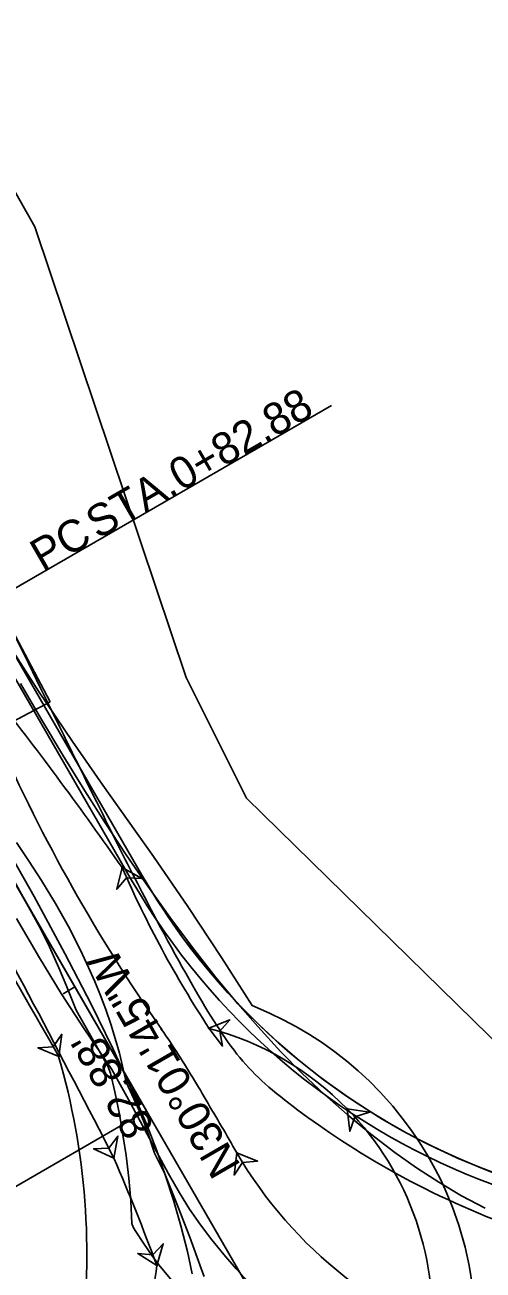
# Model space of a CAD drawing. Extents: x 208278 to 2196496, y 417130 to 637870.
# Drawn here: x 209173.8 to 209214, y 417343.4 to 417452.6 of the extents above; entities that cross this region are included whole.
import ezdxf

# ---------------------------------------------------------------- set-up
doc = ezdxf.new("R2010")
doc.units = 0
for name, color, linetype in [('BR_P_Beam', 7, 'Continuous'), ('DR_P_Ditch', 7, 'Continuous'), ('DR_P_Filter_Fabric_Fence', 7, 'Continuous'), ('DR_P_Trench_Drain', 7, 'Continuous'), ('LT_P_Conduit', 7, 'Continuous'), ('PM_P_Edge_Line', 7, 'Continuous'), ('PV_P_Saw_Cut_Line', 7, 'Continuous'), ('PV_P_Walk', 7, 'Continuous'), ('RD_P_Concrete_Barrier', 7, 'Continuous'), ('RD_P_Fence', 7, 'Continuous'), ('RD_P_Gate', 7, 'Continuous'), ('UT_P_Gas', 7, 'Continuous'), ('UT_P_Pressure Pipes', 7, 'Continuous'), ('UT_P_Sanitary', 7, 'Continuous'), ('UT_P_Water', 7, 'Continuous'), ('XS_P_Section', 7, 'Continuous')]:
    doc.layers.add(name, color=color, linetype=linetype)

msp = doc.modelspace()

# ---------------------------------------------------------------- linework, layer by layer
at = {"layer": 'BR_P_Beam'}
msp.add_line((209183.19, 417377.59), (209169.55, 417401.19), dxfattribs=at)
msp.add_line((209183.19, 417377.59), (209169.55, 417401.19), dxfattribs=at)
msp.add_arc((209236, 417408.12), 61, 210.029, 287.1031, dxfattribs=at)
at = {"layer": 'DR_P_Ditch'}
msp.add_line((209203.23, 417324.93), (209161.75, 417396.69), dxfattribs=at)
at = {"layer": 'DR_P_Filter_Fabric_Fence'}
for points in [[(209173.1, 417380.88), (209174.21, 417379.22), (209175.29, 417377.54), (209176.5, 417375.54), (209177.64, 417373.51), (209178.71, 417371.44), (209179.42, 417369.93), (209179.96, 417368.71), (209180.46, 417367.47), (209180.93, 417366.23), (209181.37, 417364.97), (209181.76, 417363.69), (209182.12, 417362.41), (209182.65, 417360.13), (209182.75, 417359.82), (209183.85, 417357.39), (209184.24, 417356.47), (209184.59, 417355.53), (209185.2, 417353.64), (209186.09, 417351.85), (209187.22, 417349.07), (209188.3, 417346.27), (209189.33, 417343.46), (209189.56, 417342.83)], [(209181.64, 417353.2), (209181.99, 417355.14), (209181.19, 417354.08), (209179.85, 417354.04), (209181.64, 417353.2)], [(209185.39, 417343.81), (209185.97, 417345.7), (209185.05, 417344.74), (209183.72, 417344.86), (209185.39, 417343.81)]]:
    msp.add_lwpolyline(points, dxfattribs=at)
for points in [[(209181.64, 417353.2), (209181.99, 417355.14), (209181.19, 417354.08), (209179.85, 417354.04)], [(209185.39, 417343.81), (209185.97, 417345.7), (209185.05, 417344.74), (209183.72, 417344.86)]]:
    msp.add_lwpolyline(points, close=True, dxfattribs=at)
for centre in [(209181.64, 417353.2), (209181.64, 417353.2), (209185.39, 417343.81), (209185.39, 417343.81)]:
    msp.add_circle(centre, 0.0417, dxfattribs=at)
for centre, radius, start, end in [((208051.5, 416772.87), 1270.43, 27.18053, 28.55626), ((209012.62, 417280.2), 184.11, 20.2135, 23.3596), ((209157.52, 417346.8), 28.03, 318.8875, 353.8854)]:
    msp.add_arc(centre, radius, start, end, dxfattribs=at)
at = {"layer": 'DR_P_Trench_Drain'}
for points in [[(209173.44, 417394.84), (209175.28, 417391.67), (209177.16, 417388.53), (209179.09, 417385.41), (209180.88, 417382.6), (209182.72, 417379.81), (209184.6, 417377.06), (209186.53, 417374.35), (209188.53, 417371.68), (209190.58, 417369.06), (209192.5, 417366.75), (209194.25, 417364.74), (209196.29, 417362.54), (209198.16, 417360.64), (209200.1, 417358.8), (209202.09, 417357.03), (209204.15, 417355.33), (209206.27, 417353.72), (209208.18, 417352.37), (209210.13, 417351.1), (209212.14, 417349.92), (209214.2, 417348.82)], [(209193.51, 417342.29), (209192.37, 417343.5), (209191.27, 417344.75), (209190.22, 417346.05), (209189.22, 417347.38), (209188.27, 417348.75), (209187.38, 417350.16), (209186.38, 417351.89), (209182.92, 417358.36), (209181.44, 417360.97), (209179.02, 417364.56), (209177.02, 417367.64), (209175.11, 417370.76), (209173.1, 417374.22)], [(209192.41, 417353.69), (209192.24, 417353.98), (209192.07, 417354.26), (209191.91, 417354.55), (209191.74, 417354.84), (209191.57, 417355.13), (209191.41, 417355.42), (209191.24, 417355.71), (209191.07, 417355.99), (209190.9, 417356.28), (209190.74, 417356.57), (209190.57, 417356.86), (209190.4, 417357.15), (209190.23, 417357.43), (209190.06, 417357.72), (209189.9, 417358.01), (209189.73, 417358.3), (209189.56, 417358.58), (209189.39, 417358.87), (209189.22, 417359.16), (209189.05, 417359.44), (209188.88, 417359.73), (209188.7, 417360.02), (209188.53, 417360.3), (209188.36, 417360.58), (209188.18, 417360.87), (209188.01, 417361.15), (209187.83, 417361.44), (209187.65, 417361.72), (209187.48, 417362), (209187.3, 417362.28), (209187.12, 417362.56), (209186.93, 417362.84), (209186.75, 417363.12), (209186.57, 417363.4), (209186.38, 417363.67), (209186.2, 417363.95), (209186.01, 417364.23), (209185.82, 417364.5)], [(209192.41, 417353.69), (209192.17, 417351.73), (209192.91, 417352.84), (209194.24, 417352.95), (209192.41, 417353.69)]]:
    msp.add_lwpolyline(points, dxfattribs=at)
msp.add_lwpolyline([(209192.41, 417353.69), (209192.17, 417351.73), (209192.91, 417352.84), (209194.24, 417352.95)], close=True, dxfattribs=at)
for centre in [(209185.82, 417364.5), (209185.82, 417364.5), (209192.41, 417353.69), (209192.41, 417353.69)]:
    msp.add_circle(centre, 0.0417, dxfattribs=at)
for centre, radius, start, end in [((209310.51, 417451.56), 152.07, 203.8397, 214.9244), ((209225.78, 417373.22), 38.67, 210.338, 253.3438)]:
    msp.add_arc(centre, radius, start, end, dxfattribs=at)
at = {"layer": 'LT_P_Conduit'}
for points in [[(209171.05, 417380.81), (209174.3, 417374.99), (209175.25, 417373.22), (209175.98, 417371.73), (209176.81, 417369.91), (209177.46, 417368.37), (209178.31, 417366.2), (209181.1, 417361.27), (209181.33, 417360.65), (209181.72, 417359.02), (209182.12, 417357.07), (209182.46, 417355.09), (209182.7, 417353.45), (209182.93, 417351.46), (209183.11, 417349.47), (209183.22, 417347.47), (209183.33, 417347.16), (209183.49, 417346.87), (209184.22, 417345.75), (209184.98, 417344.66), (209185.58, 417343.86), (209186.87, 417342.32)], [(209176.79, 417362.13), (209177.06, 417364.08), (209176.3, 417362.98), (209174.97, 417362.89), (209176.79, 417362.13)]]:
    msp.add_lwpolyline(points, dxfattribs=at)
msp.add_lwpolyline([(209176.79, 417362.13), (209177.06, 417364.08), (209176.3, 417362.98), (209174.97, 417362.89)], close=True, dxfattribs=at)
msp.add_circle((209176.79, 417362.13), 0.0417, dxfattribs=at)
msp.add_circle((209176.79, 417362.13), 0.0417, dxfattribs=at)
for centre, radius, start, end in [((212853.66, 419471.37), 4238.89, 209.40902, 209.84083), ((209117.29, 417344.79), 61.97, 352.412, 16.2407)]:
    msp.add_arc(centre, radius, start, end, dxfattribs=at)
at = {"layer": 'PM_P_Edge_Line'}
msp.add_lwpolyline([(209093.86, 417513.4), (209102.11, 417463.85), (209121.09, 417416.38), (209142.14, 417379.63), (209146.67, 417363.53), (209141.31, 417347.02), (209130.17, 417339.58), (209102, 417333.59), (209104.94, 417313.99), (209118.52, 417316.8), (209124.41, 417286.75), (209135.92, 417289.64), (209129.73, 417318.94), (209154.07, 417324.14), (209248.91, 417348.5), (209255.78, 417350.71), (209251.98, 417364.94), (209222.73, 417364.32), (209215.99, 417362.52), (209193.28, 417384.78), (209187.97, 417395.34), (209174.69, 417434.86), (209154.88, 417469.95), (209142.09, 417520.32)], dxfattribs=at)
at = {"layer": 'PV_P_Saw_Cut_Line'}
msp.add_line((209184.49, 417357.36), (209163.6, 417345.28), dxfattribs=at)
at = {"layer": 'PV_P_Walk'}
msp.add_line((209184.49, 417357.36), (209161.75, 417396.69), dxfattribs=at)
at = {"layer": 'RD_P_Concrete_Barrier'}
msp.add_open_spline([(209234.88, 417345.39), (209234.01, 417345.19), (209227.34, 417343.94), (209217.17, 417346.68), (209205.96, 417351.72), (209197.03, 417357.79), (209192.58, 417361.64), (209188.78, 417367.79), (209183.44, 417377.55), (209174.42, 417396.1), (209159.19, 417426.85), (209153.46, 417438.94), (209149.59, 417448.54), (209146.25, 417457.61), (209143.4, 417465.3), (209141.32, 417472.35), (209137.69, 417485.14), (209134.73, 417496.5), (209133.52, 417504.6), (209132.25, 417511.59), (209129.53, 417525.99), (209128.93, 417536.89), (209127.97, 417550.14), (209127.15, 417563.74), (209126.69, 417575.36), (209126.58, 417587.85), (209125.68, 417599.13), (209125.46, 417606.14), (209126.12, 417618.12), (209127.26, 417625.09), (209128.61, 417631.46), (209130.06, 417637.26), (209131.51, 417643.04), (209133.54, 417649.69), (209135.69, 417657.63), (209138.67, 417666.68), (209142.04, 417677.38), (209145.58, 417687.23), (209148, 417696), (209151.39, 417705.34), (209154.03, 417715.46), (209155.6, 417721.82), (209158.19, 417730.91), (209160.32, 417739.83), (209162.59, 417753.27), (209164.57, 417764.31), (209166.03, 417774.02), (209167.62, 417787.04), (209168.73, 417803.91), (209168.81, 417820.87), (209168.35, 417842.99), (209166.81, 417866.5), (209166.19, 417876.32), (209164.07, 417889.49), (209156.1, 417937.11), (209150.23, 417975.1), (209147.45, 417990.32), (209143.97, 418013.05), (209132.35, 418066.18), (209123, 418098.65), (209115.49, 418122.03), (209106.32, 418147.11), (209093.3, 418176.42), (209084.02, 418193.49), (209069.15, 418219.75), (209053.74, 418246), (209037.24, 418270.97), (209030.06, 418281.45), (209013.83, 418304.34), (208994.17, 418331.42), (208973.78, 418359.3), (208954.58, 418382.21), (208943.5, 418397.76), (208928.18, 418416.86), (208906.93, 418443.65), (208892.96, 418463.4), (208879.19, 418481.37), (208868.85, 418494.84), (208848.86, 418520.14), (208832.28, 418541.08), (208811.75, 418565.55), (208795.09, 418586.36), (208786.41, 418596.81), (208787.6, 418606.91), (208789.23, 418611.23), (208813.36, 418644.77)], degree=3, dxfattribs=at)
at = {"layer": 'RD_P_Fence'}
for p, q in [((209176.03, 417393.21), (209157.46, 417428.17)), ((209168.6, 417389.26), (209176.03, 417393.21))]:
    msp.add_line(p, q, dxfattribs=at)
for points in [[(209172.33, 417398.37), (209175.03, 417394.16), (209177.99, 417389.73), (209180.65, 417385.9), (209185.1, 417379.65), (209188.12, 417375.26), (209191.06, 417370.81), (209193.75, 417366.59), (209195.27, 417365.92), (209196.48, 417365.35), (209197.65, 417364.72), (209198.8, 417364.05), (209199.92, 417363.32), (209201, 417362.54), (209202.06, 417361.72), (209203.07, 417360.86), (209204.05, 417359.95), (209204.98, 417359), (209206.09, 417357.76), (209206.93, 417356.72), (209207.73, 417355.65), (209208.47, 417354.55), (209209.17, 417353.41), (209209.82, 417352.25), (209210.27, 417351.36), (209210.7, 417350.45), (209211.34, 417348.91), (209211.89, 417347.34), (209212.44, 417345.42), (209212.81, 417343.79), (209213.13, 417341.82)], [(209188.51, 417343.07), (209188.09, 417345.03), (209187.51, 417347.29), (209186.86, 417349.53), (209186.14, 417351.75), (209185.36, 417353.94), (209184.51, 417356.12), (209183.22, 417359.19), (209181.55, 417362.83), (209179.64, 417366.72), (209177.33, 417371.15), (209174.64, 417376.14), (209167.88, 417388.01)], [(209182.35, 417378.69), (209181.88, 417376.78), (209182.75, 417377.79), (209184.08, 417377.74), (209182.35, 417378.69)], [(209189.97, 417364.6), (209191.17, 417363.03), (209190.93, 417364.34), (209191.8, 417365.35), (209189.97, 417364.6)], [(209202.1, 417357.53), (209202.32, 417355.57), (209202.78, 417356.82), (209204.05, 417357.24), (209202.1, 417357.53)]]:
    msp.add_lwpolyline(points, dxfattribs=at)
for points in [[(209182.35, 417378.69), (209181.88, 417376.78), (209182.75, 417377.79), (209184.08, 417377.74)], [(209189.97, 417364.6), (209191.17, 417363.03), (209190.93, 417364.34), (209191.8, 417365.35)], [(209202.1, 417357.53), (209202.32, 417355.57), (209202.78, 417356.82), (209204.05, 417357.24)]]:
    msp.add_lwpolyline(points, close=True, dxfattribs=at)
for centre in [(209182.35, 417378.69), (209182.35, 417378.69), (209189.97, 417364.6), (209189.97, 417364.6), (209202.1, 417357.53), (209202.1, 417357.53)]:
    msp.add_circle(centre, 0.0417, dxfattribs=at)
for centre, radius, start, end in [((208918.8, 417195.14), 321.17, 34.8555, 38.133), ((209270.31, 417417.16), 96, 203.6187, 213.1938), ((209183.36, 417339.31), 26.13, 44.1973, 75.3508), ((209183.32, 417339.2), 26.25, 353.6887, 44.304)]:
    msp.add_arc(centre, radius, start, end, dxfattribs=at)
at = {"layer": 'RD_P_Gate'}
msp.add_line((209184.05, 417378.09), (209170.41, 417401.69), dxfattribs=at)
msp.add_line((209184.05, 417378.09), (209170.41, 417401.69), dxfattribs=at)
msp.add_lwpolyline([(209130.13, 418132.17), (209170.15, 417993.45), (209175.93, 417974.46), (209199.44, 417926.57), (209198.62, 417838.63), (209186.65, 417780.83), (209180.88, 417769.69), (209179.64, 417711.47), (209186.65, 417664.82), (209184.05, 417630.26), (209155.03, 417614.29), (209142.09, 417520.32), (209154.88, 417469.95), (209174.69, 417434.86), (209187.97, 417395.34), (209193.28, 417384.78), (209215.99, 417362.52), (209222.73, 417364.32), (209255.97, 417365.03), (209261.75, 417353.47), (209242.57, 417348.48)], dxfattribs=at)
for centre, radius, start, end in [((209236, 417408.12), 60, 210.029, 287.1031), ((209236, 417408.12), 60, 210.029, 244.2835), ((209236, 417408.12), 60, 244.2835, 276.2856), ((208835.85, 418789.42), 1499.08, 281.4508, 286.19452)]:
    msp.add_arc(centre, radius, start, end, dxfattribs=at)
at = {"layer": 'UT_P_Sanitary'}
msp.add_line((209161.75, 417396.69), (209200.71, 417419.21), dxfattribs=at)
at = {"layer": 'UT_P_Water'}
msp.add_line((209184.05, 417378.09), (209170.41, 417401.69), dxfattribs=at)
msp.add_line((209184.05, 417378.09), (209170.41, 417401.69), dxfattribs=at)
msp.add_arc((209236, 417408.12), 60, 210.029, 287.1031, dxfattribs=at)
at = {"layer": 'XS_P_Section'}
msp.add_line((209178.21, 417368.22), (209177.17, 417367.62), dxfattribs=at)

# ---------------------------------------------------------------- texts
at = {"layer": 'UT_P_Gas'}
msp.add_text('N30°01\'45"W', height=2.8, rotation=120.029, dxfattribs=at).set_placement((209192.81, 417352.55))
at = {"layer": 'UT_P_Pressure Pipes'}
msp.add_text("82.88'", height=2.8, rotation=120.029, dxfattribs=at).set_placement((209185.24, 417355.97))
at = {"layer": 'UT_P_Sanitary'}
for s, p in [('0+82.88', (209187.53, 417411.63)), (' STA. ', (209179.34, 417406.9)), ('PC', (209175.37, 417404.61))]:
    msp.add_text(s, height=2.8, rotation=30.029, dxfattribs=at).set_placement(p)

doc.saveas('drawing.dxf')
